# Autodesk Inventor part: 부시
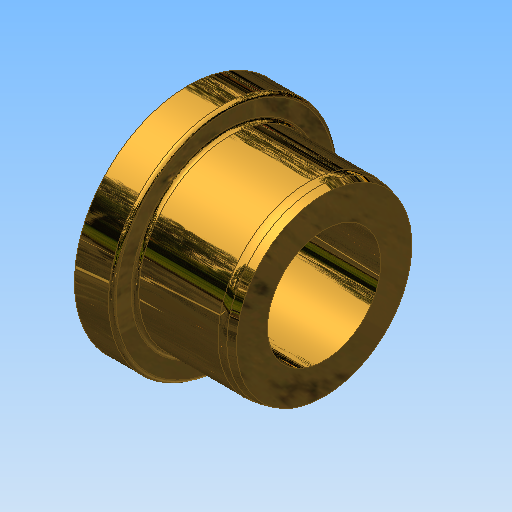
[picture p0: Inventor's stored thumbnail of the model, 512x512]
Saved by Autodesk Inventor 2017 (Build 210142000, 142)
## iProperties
Created: 2016-05
Part Number: 부시
Document SubType Name: Modeling
Designer: mduedu
Density: 7.86 g/cm^3
Material: 강철, 연강
Appearance: 황동 - 새틴
Author: mduedu
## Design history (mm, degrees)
sketch "스케치1"
  geometry: L1 (0, 0)-(18, 0); L2 (1.5, 7.5)-(18, 7.5); L3 (18, 7.5)-(18, 11.598); L4 (16.5, 12)-(5, 12); L5 (5, 12)-(5, 15); L6 (5, 15)-(0, 15); L7 (0, 15)-(0, 7.902); L8 (0, 7.902)-(1.5, 7.5); L9 (16.5, 12)-(18, 11.598)
  constraints: 18 end point, 4 parallel, 1 horizontal, 1 perpendicular, 1 point on line, 1 vertical, 1 vertical alignment
  dimensions: "d0" = 18 distance of L1.start L1.end; "d1" = 15 diameter of L2 L1; "d2" = 24 diameter of L4 L1; "d3" = 5 distance of L5.end L6.end; "d4" = 30 diameter of L6 L1; "d9" = 15 deg angle of L2 L8; "d10" = 1.5 horizontal distance of L7.end L2.start; "d13" = 15 deg angle of L4 L9; "d14" = 1.5 distance from line of L4.start L3
revolve "회전1" sketch "스케치1" stored, may be unused: angle "d5" = 90 deg
fillet "모깎기1" dims "d11" = 4
fillet "모깎기2" dims "d12" = 0.5
node "솔리드1"
